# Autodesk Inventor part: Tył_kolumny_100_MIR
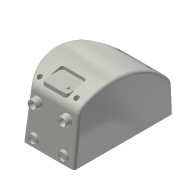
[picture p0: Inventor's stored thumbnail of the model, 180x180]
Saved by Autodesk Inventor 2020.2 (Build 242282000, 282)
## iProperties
Created: 2010-12
Part Number: Tył_kolumny_100_MIR
Document SubType Name: Modeling
Designer: F.Stasiak
Density: 1 g/cm^3
Material: Ogólny
Appearance: Gładkie — w kolorze kości słoniowej
Manager: www.cadconsulting.pl
Company: Fabian Stasiak CAD Consulting
Author: F.Stasiak
Subject: Zbiór ćwiczeń. Autodesk Inventor 2020. Kurs podstawowy
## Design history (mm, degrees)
derived "Tył_kolumny_100.ipt"
  sketch "Szkic2"
    geometry: L1 (0, 6.364)-(0, 0) reference; L2 (0, 0)-(4.995, 0) reference; L3 (97.719, 0)-(100, 0) reference; L4 (63.707, 200)-(65.027, 200) reference; L5 (0, 195.005)-(0, 200) reference; L6 (0, 200)-(4.995, 200) reference; L7 (97.719, 0)-(4.995, 0) reference; L8 (0, 195.005)-(0, 6.364) reference; L9 (4.995, 200)-(63.707, 200) reference; A1 r 130 centre (2.514, 86.002) between (100, 0) and (101.523, 1.758) reference; A2 r 130 centre (129.792, 312.719) between (65.027, 200) and (66.153, 199.361) reference; A3 r 130 centre (2.514, 86.002) between (101.523, 1.758) and (66.153, 199.361) reference; 1 further point
  sketch "Szkic3"
    geometry: L1 (-200, 0)-(-200, -110) reference; L2 (0, 0)-(0, -110) reference; A1 r 145.689 centre (-80.112, 27.778) between (-200, -55) and (0, -93.908) reference
  sketch "Szkic6"
    geometry: L1 (-81.347, -15)-(-21.347, -15) reference; L2 (-21.347, -15)-(-21.347, -75) reference; L3 (-21.347, -75)-(-81.347, -75) reference; L4 (-81.347, -75)-(-81.347, -15) reference; L5 (-97.729, 0)-(-5, 0) reference; C1 r 9 at (-81.347, -15) reference; C2 r 9 at (-21.347, -15) reference; C3 r 9 at (-81.347, -75) reference; C4 r 9 at (-21.347, -75) reference; C5 r 7 at (-81.347, -15) reference; C6 r 7 at (-21.347, -15) reference; C7 r 7 at (-81.347, -75) reference; C8 r 7 at (-21.347, -75) reference; 3 further points
  sketch "Szkic8"
    geometry: L1 (92.492, 23.503)-(92.492, 2.565) reference; L2 (92.492, 23.503)-(111.002, 23.503) reference; L3 (18.503, 23.503)-(18.503, 2.565) reference; L4 (18.503, 23.503)-(-0.006, 23.503) reference; L5 (75.095, 166.497)-(100.905, 166.497) reference; L6 (15.503, 166.497)-(2.13, 166.497) reference; 1 further point
  sketch "Szkic9"
    geometry: L1 (0, 189.388)-(0, 23.205) reference; L2 (97.468, 4.045)-(5, 4.045) reference; L3 (3.5, 5.553)-(3.5, 194.777) reference; L4 (5, 196.278)-(62.98, 196.278) reference; L5 (0, 194.777)-(0, 5.553) reference; L6 (5, 0.526)-(18.771, 0.526) reference; L7 (63.001, 199.782)-(5, 199.782) reference; L8 (3.5, 100.165)-(127.67, 100.165) reference; L9 (3.5, 135.165)-(8.5, 135.165) reference; L10 (3.5, 65.165)-(8.5, 65.165) reference; L11 (118.478, 135.165)-(108.478, 135.165) reference; L12 (126.733, 65.165)-(116.733, 65.165) reference; L13 (34.001, 194.777)-(34.001, 189.777) reference; L14 (51.234, 4.045)-(51.234, 12.045) reference; L15 (23.923, 0.526)-(78.771, 0.526) reference; L16 (83.923, 0.526)-(97.486, 0.526) reference; A1 r 125.955 centre (2.514, 86.002) between (98.606, 4.572) and (63.718, 196.088) reference; A2 r 129.474 centre (2.514, 86.002) between (101.279, 2.283) and (65.461, 199.145) reference; 5 further points; 4 other entities
    constraints: 4 other
  sketch "SZKIC KOMINKÓW MONTAŻOWYCH"
    geometry: 5 further points
  sketch "SZKIC PÓŁKI"
    geometry: L1 (75.498, 56.503)-(35.498, 56.503) reference; L2 (30.498, 51.503)-(30.498, 21.503) reference; L3 (35.498, 16.503)-(75.498, 16.503) reference; L4 (80.498, 21.503)-(80.498, 51.503) reference; L5 (92.492, 23.503)-(18.503, 23.503) reference; A1 r 5 centre (35.498, 51.503) between (35.498, 56.503) and (30.498, 51.503) reference; A2 r 5 centre (75.498, 51.503) between (80.498, 51.503) and (75.498, 56.503) reference; A3 r 5 centre (35.498, 21.503) between (30.498, 21.503) and (35.498, 16.503) reference; A4 r 5 centre (75.498, 21.503) between (75.498, 16.503) and (80.498, 21.503) reference; 6 further points
  sketch "Szkic14"
    geometry: L1 (-37.617, -32.643)-(-33.617, -32.643) reference; L2 (-33.617, -32.643)-(-33.617, -27.643) reference; L3 (-33.617, -27.643)-(-37.617, -27.643) reference; L4 (-37.617, -27.643)-(-37.617, -32.643) reference; 1 further point
  sketch "Szkic15"
    geometry: L1 (-37.617, -27.643)-(-37.617, -32.643) reference; L2 (-33.617, -32.643)-(-33.617, -27.643) reference; 3 further points
  node "Płaszczyzna konstrukcyjna1"
  node "Płaszczyzna konstrukcyjna2"
  node "Płaszczyzna konstrukcyjna3"
  node "Płaszczyzna konstrukcyjna4"
feature "Bryła1::Tył_kolumny_100.ipt" dims "d0" = 10
feature "Srf1::Tył_kolumny_100.ipt"
body "Srf1"
tag "Bryła wyprowadzona1"
node "Bryła1"
